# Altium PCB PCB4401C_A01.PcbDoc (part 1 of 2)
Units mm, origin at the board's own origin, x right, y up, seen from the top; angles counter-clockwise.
Board outline 30 x 49 mm, 4 copper layers (Top Layer, Signal Layer 2, Signal Layer 3, Bottom Layer), stack 1.6 mm thick; 91 components, 90 nets, 342 pads, 490 vias.
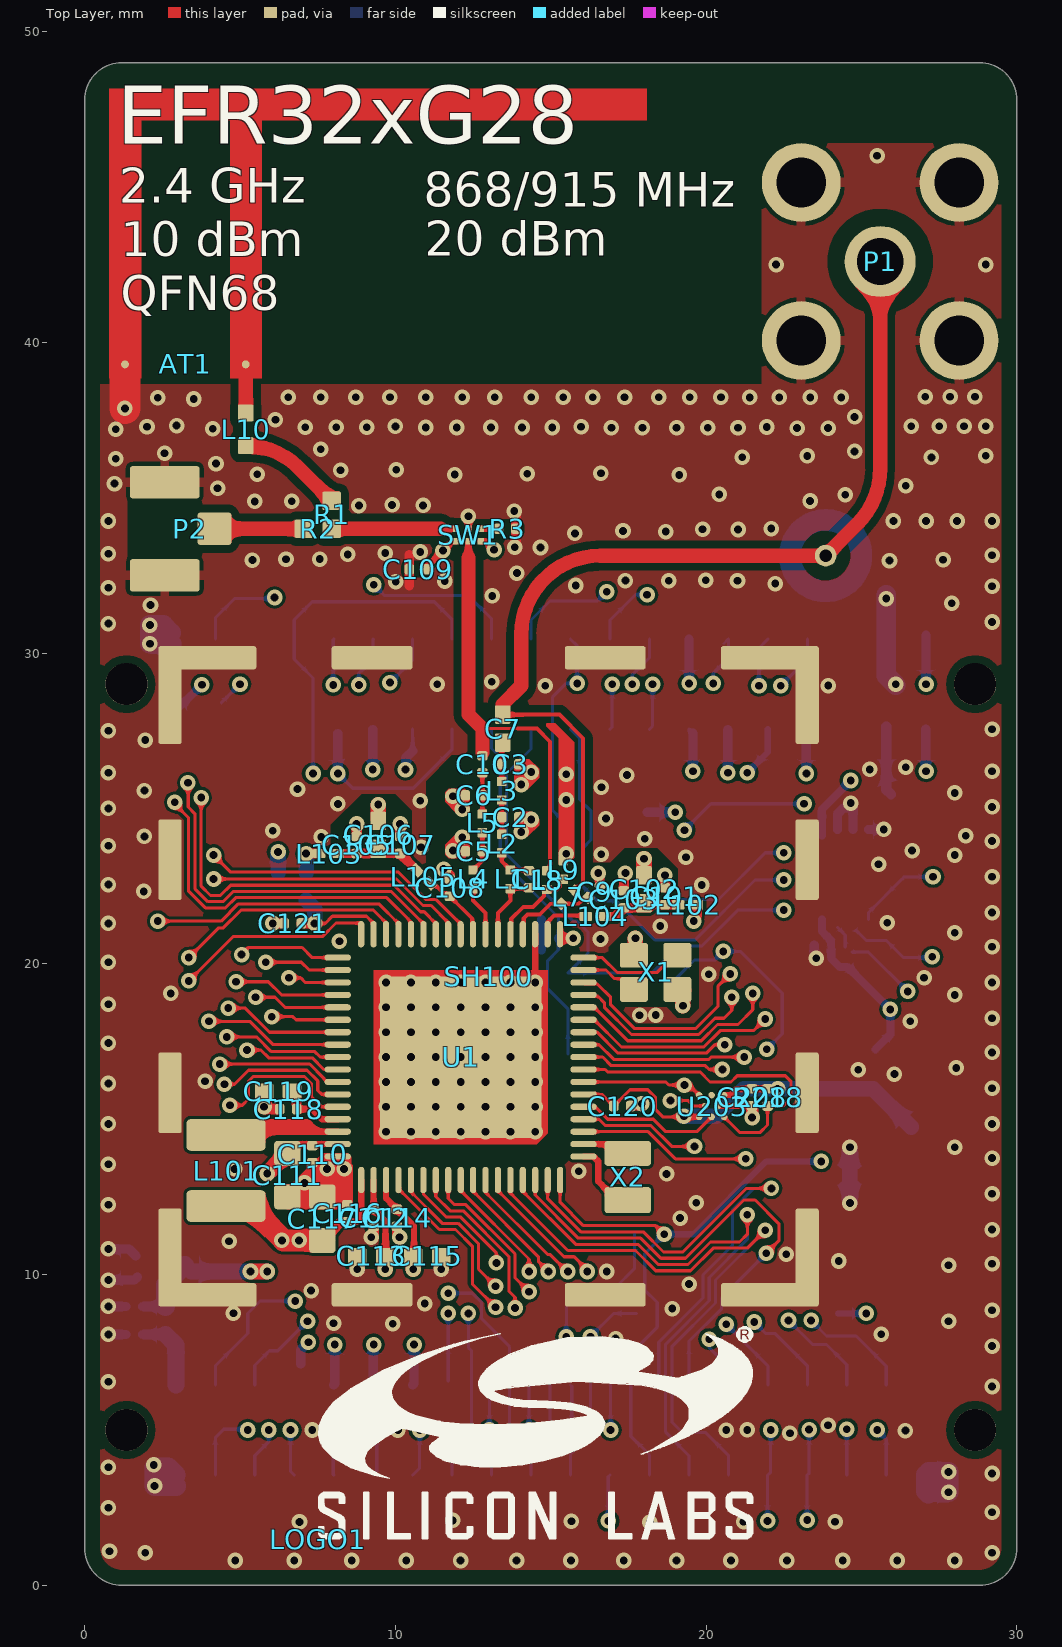
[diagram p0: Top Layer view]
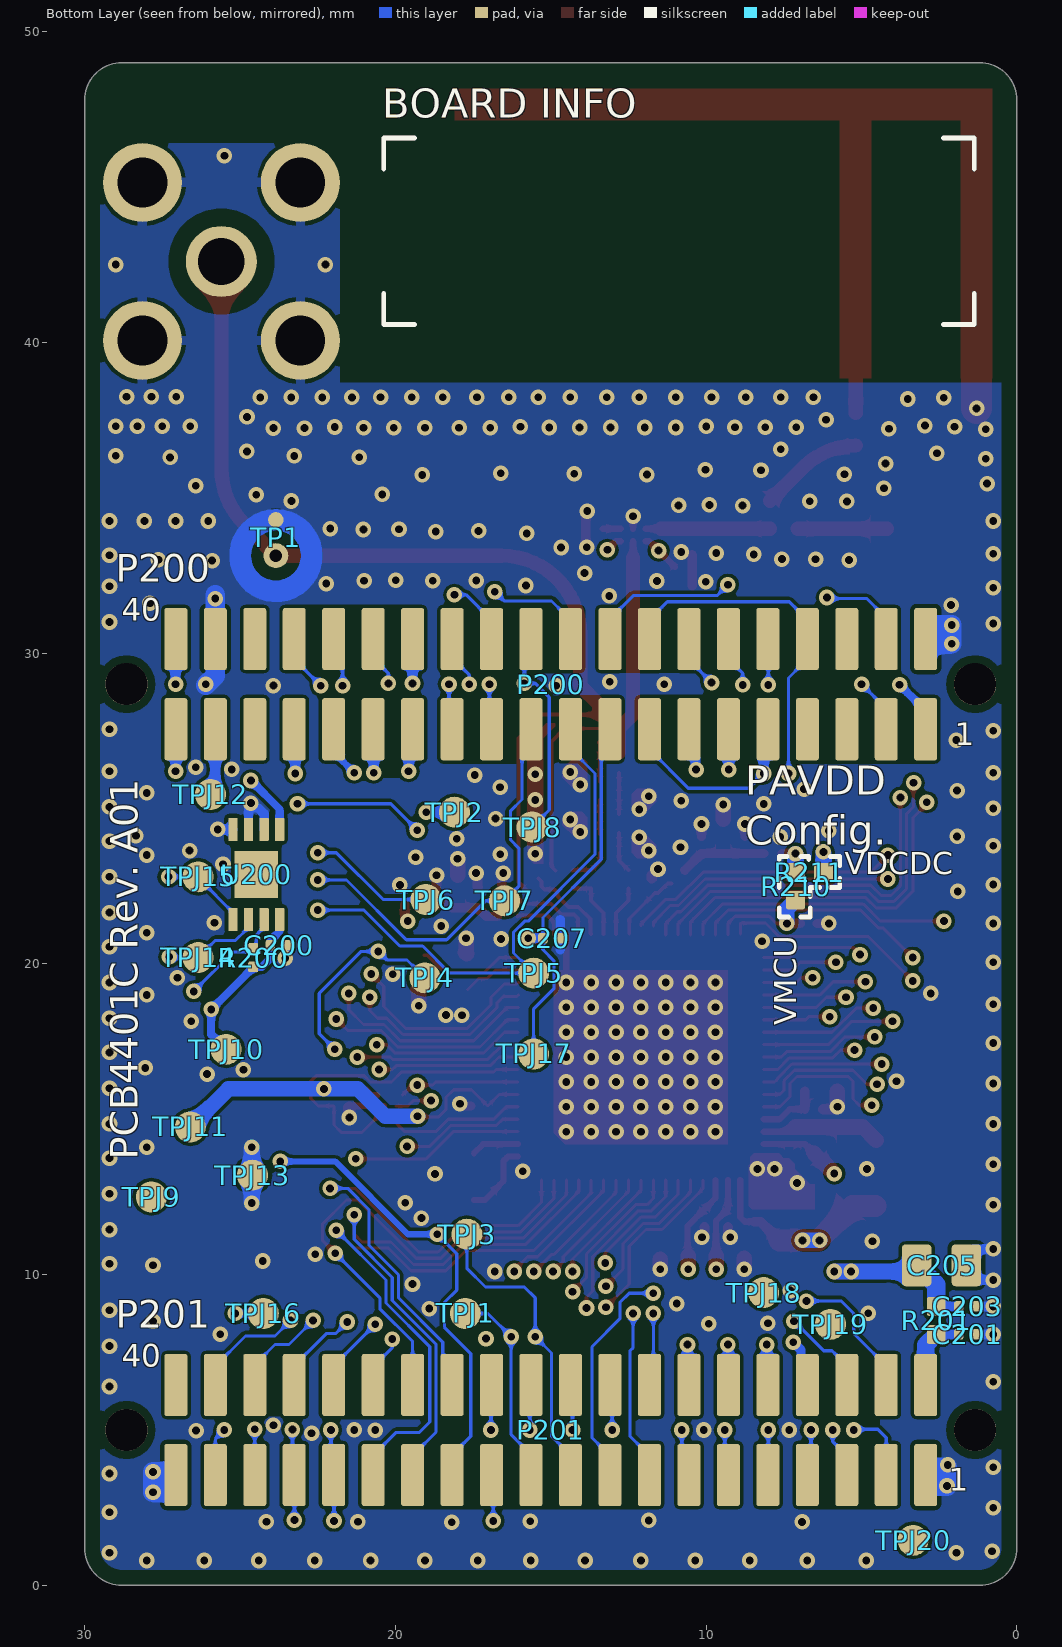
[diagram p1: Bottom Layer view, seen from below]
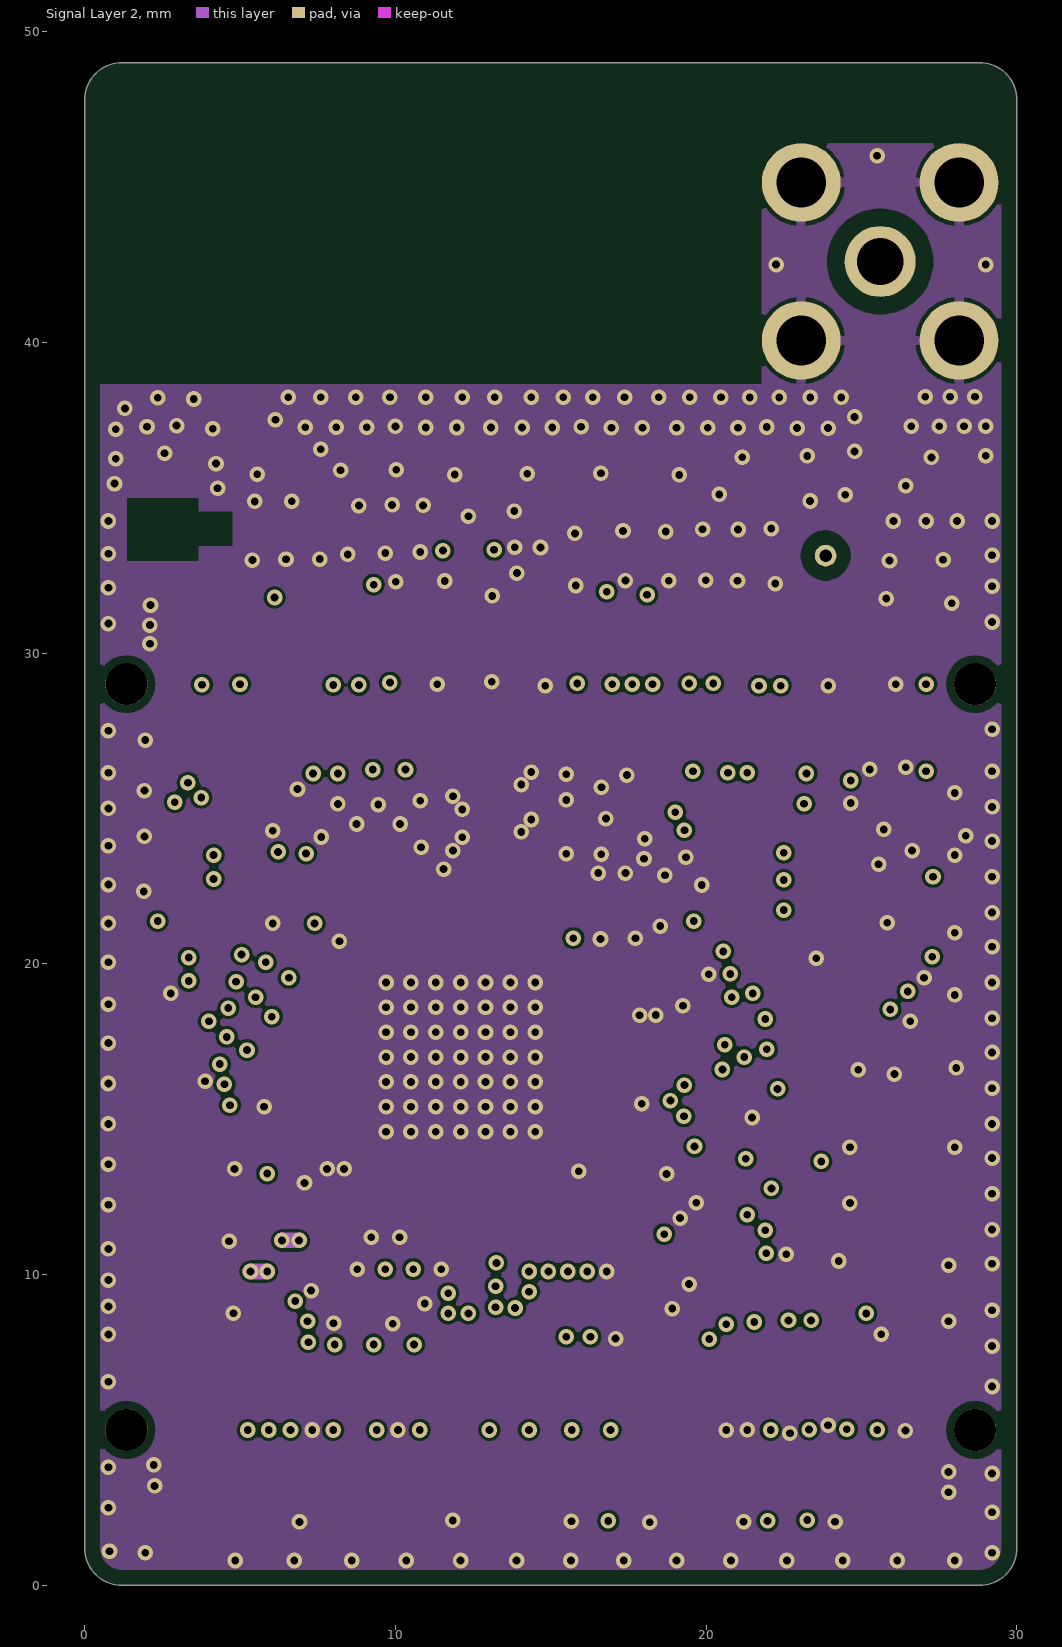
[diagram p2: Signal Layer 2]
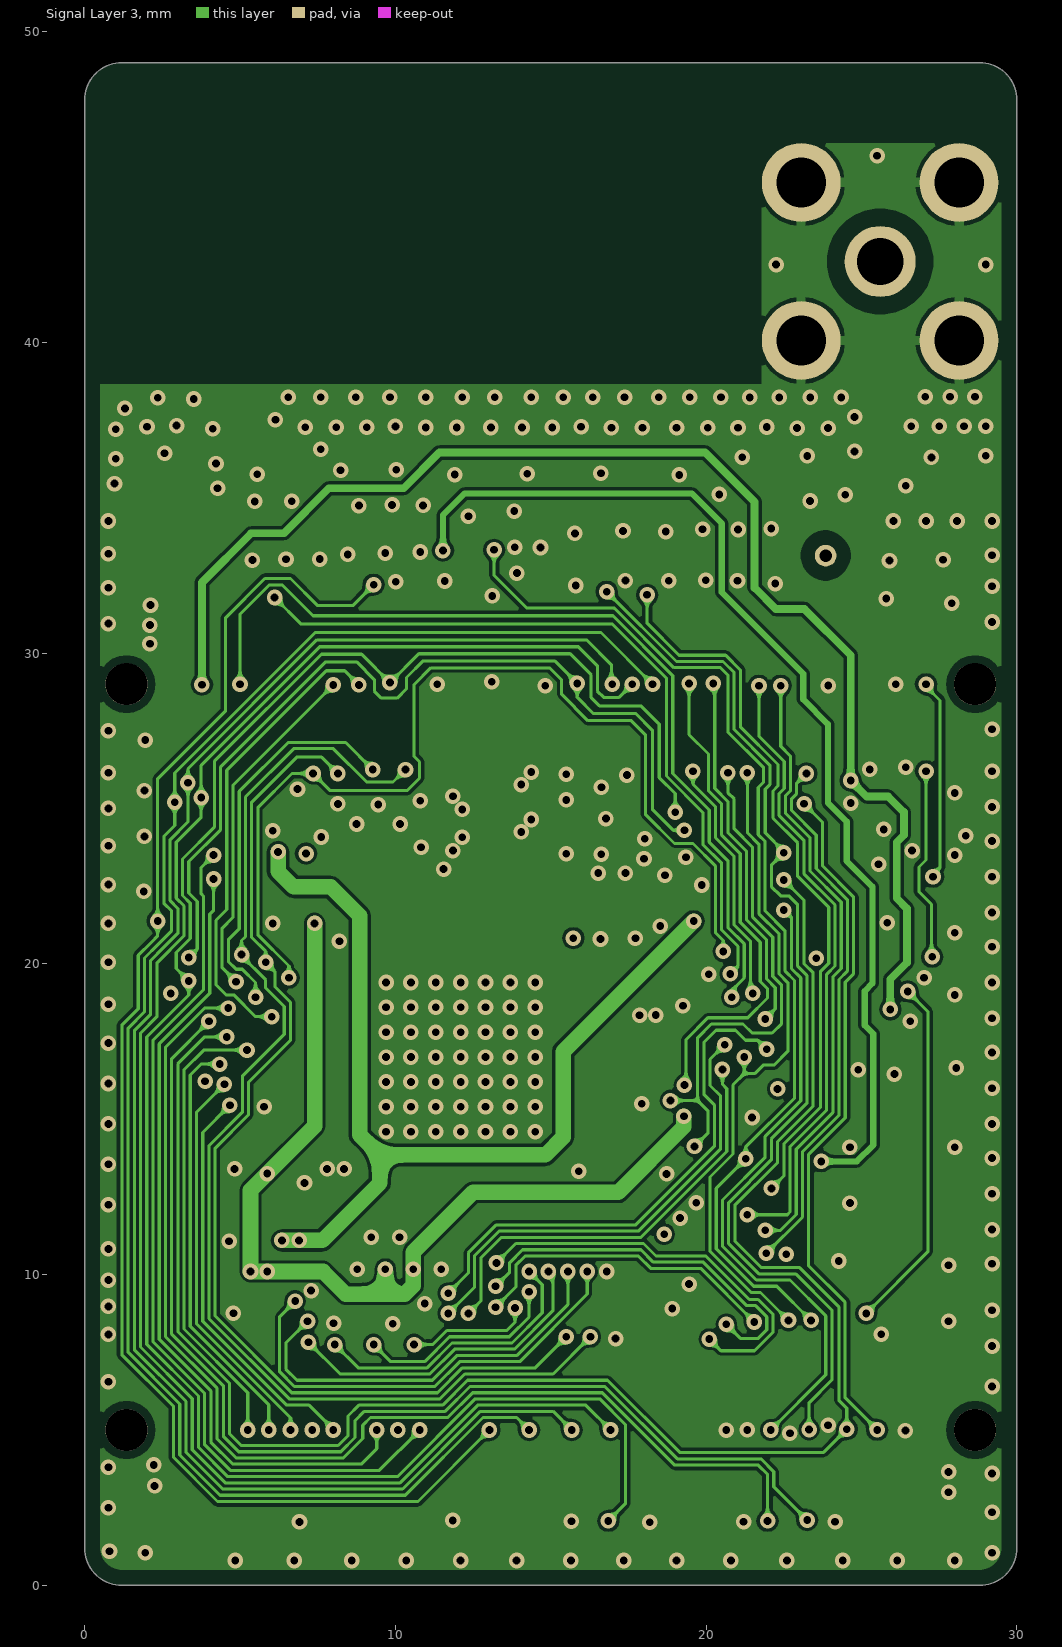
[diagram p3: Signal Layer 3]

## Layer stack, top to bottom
Top Solder: solder mask 0.0102, Solder Resist, Dk 3.5
Top Layer: signal copper 0.035
Dielectric 1: core 0.325, FR-4, Dk 4.2
Signal Layer 2: signal copper 0.018
Dielectric 3: prepreg 0.844, Dk 4.2
Signal Layer 3: signal copper 0.018
Dielectric 2: core 0.325, Dk 4.2
Bottom Layer: signal copper 0.035
Bottom Solder: solder mask 0.0102, Solder Resist, Dk 3.5

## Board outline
0,1.2 0,47.8 cw(c1.2,47.8) 1.2,49 28.8,49 cw(c28.8,47.8) 30,47.8 30,1.2 cw(c28.8,1.2) 28.8,0 1.2,0 cw(c1.2,1.2)

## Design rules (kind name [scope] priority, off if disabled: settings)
AcuteAngle [All] p1: minimum=7.00000000000000E+0001 checktracksonly=FALSE
BoardOutlineClearance [All] p1: gap=0.5 ignorepadtopadclearanceinfootprint=FALSE
Clearance Clearance_50Ohm [InNet('50R*') vs InNet('GND')] p1: gap=0.1 ignorepadtopadclearanceinfootprint=FALSE except(0: Arc-Hole Track-Hole SMDPad-Hole THPad-Hole Via-Hole Fill-Hole Poly-Hole Region-Hole Text-Hole; 0.254: Arc-Poly Track-Poly SMDPad-Poly THPad-Poly Via-Poly Fill-Poly Poly-Poly Poly-Region Poly-Text)
Clearance Clearance_to_Holes [InPadClass('NPTH')] p2: gap=0.254 ignorepadtopadclearanceinfootprint=FALSE except(0: Arc-Hole Track-Hole SMDPad-Hole THPad-Hole Via-Hole Fill-Hole Poly-Hole Region-Hole Text-Hole)
Clearance Clerance_Polygon [InPolygon] p3: gap=0.1 ignorepadtopadclearanceinfootprint=FALSE except(0: Arc-Hole Track-Hole SMDPad-Hole THPad-Hole Via-Hole Fill-Hole Poly-Hole Region-Hole Text-Hole)
Clearance Clearance_General [All] p4: gap=0.1 ignorepadtopadclearanceinfootprint=FALSE except(0: Arc-Hole Track-Hole SMDPad-Hole THPad-Hole Via-Hole Fill-Hole Poly-Hole Region-Hole Text-Hole)
HoleToHoleClearance HoleToHoleClearance_ANT1toPAD [Incomponent ('ANT1') vs ISpad] p1: gap=0 allowstackedmicrovias=TRUE
HoleToHoleClearance HoleToHoleClearance_R1toR2_1 [Incomponent ('R1') vs Incomponent ('R2')] p2: gap=0 allowstackedmicrovias=TRUE
HoleToHoleClearance HoleToHoleClearance_U1toVIA_1 [InComponent ('U1') vs IsVia] p3: gap=0 allowstackedmicrovias=TRUE
HoleToHoleClearance [All] p4: gap=0.254 allowstackedmicrovias=TRUE
MinimumSolderMaskSliver [All] p1: minsoldermaskwidth=0.075
PolygonConnect Polygon_VIA_Connect [IsVia] p1: connectstyle=Direct reliefconductorwidth=0.254 reliefentries=4 polygonreliefangle="90 Angle" airgapwidth=0.254
PolygonConnect PolygonConnect_SH100 [InComponent('SH100')] p2: connectstyle=Direct reliefconductorwidth=0.254 reliefentries=4 polygonreliefangle="90 Angle" airgapwidth=0.127
PolygonConnect PolygonConnect_P1 [InComponent('P1', 'P2')] p3: connectstyle=Relief reliefconductorwidth=0.3 reliefentries=4 polygonreliefangle="90 Angle" airgapwidth=0.127
PolygonConnect [All] p4: connectstyle=NoConnect reliefconductorwidth=0.2 reliefentries=4 polygonreliefangle="90 Angle" airgapwidth=0.125
RoutingVias [All] p1: holewidth=0.3 width=0.65 viastyle="Through Hole" minholewidth=0.25 minwidth=0.5 maxholewidth=1 maxwidth=1.5
ShortCircuit ShortCircuit_ANTtoPAD [InNet('NetAT1_1') vs InNet('GND')] p1: allowed=TRUE
ShortCircuit ShortCircuit_R1toR2_1 [Incomponent ('R1') vs Incomponent ('R2')] p2: allowed=TRUE
ShortCircuit [All] p3: allowed=FALSE
SilkToSilkClearance [All] p1: silktosilkclearance=0.102
SilkToSolderMaskClearance [IsPad] p1: minsilkscreentomaskgap=0.102 clearancetoexposedcopper=TRUE
SolderMaskExpansion [All] p1: expansion=0.051 istentingtop=FALSE
Width 50ohm [InNet('50R*')] p1: maxlimit=0.457 minlimit=0.1 preferedwidth=0.457
Width [All] p2: maxlimit=5.08 minlimit=0.1 preferedwidth=0.125
25 further rules are at their usual default settings.

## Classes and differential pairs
pad class NPTH: P200-M1 P200-M2 P201-M1 P201-M2

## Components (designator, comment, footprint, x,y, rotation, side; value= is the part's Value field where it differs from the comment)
AT1 "INVERTED_F" ANT_INV_F_2.4_GHZ_17.3MM_MIR 0.79,38.84 r0 top locked net-tie
C1 "2P0" C0201_L 14.3,22.72 r90 top
C2 "7P6" C0201_L 13.7,24.72 r0 top
C3 "1P3" C0201_L 13.7,26.42 r180 top
C5 "1P0" C0201_L 12.525,23.62 r180 top
C6 "0P3" C0201_L 12.525,25.42 r0 top
C7 "220P" C0402_L 13.45,27.57 r90 top
C9 "TBD" C0201_L 16.4,22.32 r225 top
C10 "18P" C0201_L 12.8,26.42 r270 top
C101 "TBD" C0201_L 18.675,22.175 r90 top
C102 "1U" C0402_L 18,22.4 r90 top
C103 "100P" C0201_L 17.35,22.075 r90 top
C105 "TBD" C0201_L 8.75,23.825 r90 top
C106 "470N" C0402_L 9.45,24.15 r90 top
C107 "100P" C0201_L 10.15,23.825 r90 top
C108 "100P" C0201_L 11.75,22.45 r90 top
C109 "100P" C0201_L 10.724,32.695 r180 top
C110 "100N" C0201_L 7.325,13.875 r270 top
C111 "10U" C0603_L 6.525,13.2 r270 top
C112 "10N" C0201_L 9.3,11.825 r270 top
C113 "1U" C0402_L 9.225,10.6 r180 top
C114 "100N" C0201_L 10.05,11.825 r270 top
C115 "1U" C0402_L 11.025,10.6 r0 top
C116 "100N" C0201_L 8.45,11.975 r90 top
C117 "4U7" C0603_L 7.65,11.8 r90 top
C118 "100N" C0201_L 6.55,15.325 r180 top
C119 "1U" C0402_L 6.225,15.9 r180 top
C120 "100N" C0201_L 17.3,15.425 r0 top
C121 "100N" C0201_L 6.7,21.3 r180 top
C200 "100N" C0201_L 23.75,20.6 r180 bottom
C201 "100N" C0201_L 1.6,8.075 r180 bottom
C203 "100N" C0201_L 1.6,8.975 r180 bottom
C205 "10U" C0805_L 2.425,10.3 r180 bottom
C207 "100N" C0201_L 14.975,20.825 r180 bottom
C208 "100N" C0201_L 21.475,15.7 r270 top
Designator39 "Comment" PCB_SPEC_4_LAYER -68.7,108.2 r0 top
L1 "1N5" COIL_0201_L 13.7,22.72 r90 top
L2 "1N3" COIL_0201_L 13.425,23.87 r90 top
L3 "13N" COIL_0201_L 13.425,25.57 r90 top
L4 "3N0" COIL_0201_L 12.5,22.72 r90 top
L5 "8N2" COIL_0201_L 12.8,24.52 r90 top
L7 "18N" COIL_0201_L 15.55,22.145 r45 top
L8 "3N1" COIL_0201_L 14.875,22.695 r90 top
L9 "1N8" COIL_0201_L 15.4,23.02 r90 top
L10 "0R" COIL_0402_L 5.184,37.2 r90 top
L101 "2U2" COIL_1008_L 4.55,13.35 r270 top
L102 "BLM03AG700SN1D" COIL_MUR_BLM03_0201 19.4,21.9 r0 top
L103 "0R" COIL_MUR_BLM03_0201 7.85,23.55 r180 top
L104 "0R" COIL_MUR_BLM03_0201 16.425,21.525 r180 top
L105 "BLM03PG330SN1D" COIL_MUR_BLM03_0201 10.9,22.8 r315 top
LOGO1 "Comment" LOGO_SILABS_W14.0 7.501,1.49 r0 top
P1 "SMA" TE_SMA_1814832_TH_VER 25.6,42.6 r0 top
P2 "U.FL" COAX_HIROSE_U.FL_CL331-0471 2.578,34 r270 top
P200 "SOCKET_WCON_2X20_1.27MM_SMD" SAM_SFC-120-T2-D-A-2X20_SNUM 15,29 r0 bottom locked
P201 "SOCKET_WCON_2X20_1.27MM_SMD" SAM_SFC-120-T2-D-A-2X20_SNUM 15,5 r0 bottom locked
R1 "0R" R0402_L 7.95,34.45 r90 top
R2 "0R" R0402_L 7.5,34 r180 top
R3 "50R" R0201_L#1 13.6,34 r0 top
R200 "10K" R0201_L#2 24.575,20.2 r270 bottom
R201 "0R" R0402_L 2.6,8.525 r90 bottom
R210 "0R" R0402_L 7.125,22.5 r270 bottom
R211 "0R" R0402_L 6.675,22.95 r0 bottom
R218 "330K" R0201_L#1 21.975,15.7 r90 top
SH100 "RF_SHIELD_FRAME_36103205S" shield_21x21mm 13,19.6 r0 top locked
SW1 "BGS12WN6" XFDFN-6 12.35,33.8 r180 top
TP1 "TP_RF" "TP_INGUN_50_OHM_CLOSED OPENVIA" 23.845,33.135 r0 bottom
TPJ1 "TPJ_SMD" TP_1.0_SMD 17.75,8.75 r90 bottom locked
TPJ2 "TPJ_SMD" TP_1.0_SMD 18.1,24.88 r90 bottom locked
TPJ3 "TPJ_SMD" TP_1.0_SMD 17.7,11.3 r90 bottom locked
TPJ4 "TPJ_SMD" TP_1.0_SMD 19.05,19.55 r90 bottom locked
TPJ5 "TPJ_SMD" TP_1.0_SMD 15.55,19.7 r90 bottom locked
TPJ6 "TPJ_SMD" TP_1.0_SMD 19.02,22.07 r90 bottom locked
TPJ7 "TPJ_SMD" TP_1.0_SMD 16.49,22.03 r90 bottom locked
TPJ8 "TPJ_SMD" TP_1.0_SMD 15.6,24.4 r90 bottom locked
TPJ9 "TPJ_SMD" TP_1.0_SMD 27.85,12.5 r90 bottom locked
TPJ10 "TPJ_SMD" TP_1.0_SMD 25.45,17.25 r90 bottom locked
TPJ11 "TPJ_SMD" TP_1.0_SMD 26.6,14.75 r90 bottom locked
TPJ12 "TPJ_SMD" TP_1.0_SMD 25.95,25.45 r90 bottom locked
TPJ13 "TPJ_SMD" TP_1.0_SMD 24.6,13.2 r90 bottom locked
TPJ14 "TPJ_SMD" TP_1.0_SMD 26.35,20.2 r90 bottom locked
TPJ15 "TPJ_SMD" TP_1.0_SMD 26.35,22.8 r90 bottom locked
TPJ16 "TPJ_SMD" TP_1.0_SMD 24.25,8.75 r90 bottom locked
TPJ17 "TPJ_SMD" TP_1.0_SMD 15.55,17.1 r90 bottom locked
TPJ18 "TPJ_SMD" TP_1.0_SMD 8.15,9.42 r90 bottom locked
TPJ19 "TPJ_SMD" TP_1.0_SMD 6,8.4 r90 bottom locked
TPJ20 "TPJ_SMD" TP_1.0_SMD 3.34,1.45 r90 bottom locked
U1 "EFR32ZG28B322F1024IM68" QFN68_M040_8.0X8.0_EP_SL 12.1,17 r180 top
U200 "M24C02" TDFN8_M050_2.0X3.0_EP 24.475,22.875 r270 bottom
U203 "MX25R8035F" BGA8_M040_1.24X1.75_WLCSP 20.175,15.425 r270 top
X1 "39.000 MHz" KDS_DSX211SH_2016 18.375,19.725 r180 top
X2 "32.768 kHz" X_MCS_CM8V-T1A 17.475,13.15 r270 top

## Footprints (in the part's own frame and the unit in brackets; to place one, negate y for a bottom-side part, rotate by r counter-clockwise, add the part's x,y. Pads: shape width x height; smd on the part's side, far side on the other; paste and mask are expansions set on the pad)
ANT_INV_F_2.4_GHZ_17.3MM_MIR [mil] "Antenna inverted F, 2.4 GHz, 17.3 mm (MIR)"
  round 10 smd paste-5.04 mask-5.04: 1(173,17.72) 2(20.01,17.72)
  Top Layer region: 0.36,367.2 681,367.2 681,327.07 193.36,327.07 193.36,0 153.36,0 153.36,327.07 40.36,327.07 40.36,0 20.36,0 0.36,0
BGA8_M040_1.24X1.75_WLCSP [mm] "BGA, 8 pin. U100"
  round 0.21 smd mask+0.038: A1(-0.35,0.4) A3(0.35,0.4) B2(0,0.2) C1(-0.35,0) C3(0.35,0) D2(0,-0.2) E1(-0.35,-0.4) E3(0.35,-0.4)
  body extent -0.63,-0.89 0.63,0.88, height 0.52
C0201_L [mm] "Capacitor, Chip; 0.60 mm L X 0.30 mm W X 0.33 mm H body"
  rrect52% 0.31x0.34 smd: 1(-0.275,0) 2(0.275,0)
  body extent -0.3,-0.15 0.3,0.15, height 0.3
C0402_L [mm] "Chip Capacitor, 2-Leads, Body 1.0x0.5mm, IPC High Density"
  rrect20% 0.6x0.5 smd mask+0.051: 1(-0.45,0) 2(0.45,0)
  body extent -0.5,-0.25 0.5,0.25, height 0.6
C0603_L [mm] "Capacitor, 0603, High Density (C)"
  rrect25% 0.8x0.85 smd: 1(-0.7,0) 2(0.7,0)
  body extent -0.8,-0.4 0.8,0.4, height 0.95
C0805_L [mm] "Capacitor, 0805"
  rrect25% 0.95x1.35 smd: 1(-0.8,0) 2(0.8,0)
  body extent -1.1,-0.72 1.1,0.72, height 1.45
COAX_HIROSE_U.FL_CL331-0471 [mm] "COAX_HIROSE_U.FL_CL331-0471"
  rrect20% 1.05x1.1 smd mask+0.051: 1(0,1.6)
  rrect20% 1.05x2.25 smd mask+0.051: 2(-1.5,0) 3(1.5,0)
  Top Layer pour cut-out: -0.85,0.9 0.85,0.9 0.85,0.9 0.85,-1.2 -0.85,-1.2 -0.85,-1.2
  body extent -1.3,-1.55 1.3,1.3, height 0.9
COIL_0201_L [mm] "JELF243C-0021"
  rrect10% 0.3x0.3 smd: 1(-0.3,0) 2(0.3,0)
  body extent -0.32,-0.17 0.32,0.17, height 0.33
COIL_0402_L [mm] "COIL_0402_L"
  rrect20% 0.55x0.5 smd mask+0.051: 1(-0.525,0) 2(0.525,0)
  body extent -0.5,-0.25 0.5,0.25, height 0.5
COIL_1008_L [mil] "Chip Inductors, 1008 (2520), Coilcraft (190207)"
  rrect25% 40x100 smd: 1(-45,0) 2(45,0)
  body extent -58,-55 57,55, height 80
COIL_MUR_BLM03_0201 [mm] "COIL_MUR_BLM03_0201"
  rrect25% 0.4x0.3 smd mask+0.051: 1(-0.3,0) 2(0.3,0)
  body extent -0.3,-0.15 0.3,0.15, height 0.95
KDS_DSX211SH_2016 [mm] "Copy of Silabs CE  X_KDS_DSX211SH_2.0X1.65-4"
  rrect20% 0.9x0.8 smd mask+0.051: 1(-0.7,-0.55) 2(0.7,-0.55) 3(0.7,0.55) 4(-0.7,0.55)
  body extent -1.07,-0.87 1.08,0.88, height 0.5
LOGO_SILABS_W14.0 [mm] "LOGO_SILABS_W14.0"
  silkscreen extent 0.03,0 13.99,6.83
PCB_SPEC_4_LAYER [mm]
QFN68_M040_8.0X8.0_EP_SL [mm]
  rrect5% 5.2x5.2 smd paste-4.2 mask-4.2: 0(0,0)
  oval 0.85x0.2 smd paste+0 mask+0.06: 1(-3.955,3.2) 2(-3.955,2.8) 3(-3.955,2.4) 4(-3.955,2) 5(-3.955,1.6) 6(-3.955,1.2) 7(-3.955,0.8) 8(-3.955,0.4) 9(-3.955,0) 10(-3.955,-0.4) 11(-3.955,-0.8) 12(-3.955,-1.2) 13(-3.955,-1.6) 14(-3.955,-2) 15(-3.955,-2.4) 16(-3.955,-2.8) 17(-3.955,-3.2) 35(3.955,-3.2) 36(3.955,-2.8) 37(3.955,-2.4) 38(3.955,-2) 39(3.955,-1.6) 40(3.955,-1.2) 41(3.955,-0.8) 42(3.955,-0.4) 43(3.955,0) 44(3.955,0.4) 45(3.955,0.8) 46(3.955,1.2) 47(3.955,1.6) 48(3.955,2) 49(3.955,2.4) 50(3.955,2.8) 51(3.955,3.2)
  oval 0.2x0.85 smd paste+0 mask+0.06: 18(-3.2,-3.955) 19(-2.8,-3.955) 20(-2.4,-3.955) 21(-2,-3.955) 22(-1.6,-3.955) 23(-1.2,-3.955) 24(-0.8,-3.955) 25(-0.4,-3.955) 26(0,-3.955) 27(0.4,-3.955) 28(0.8,-3.955) 29(1.2,-3.955) 30(1.6,-3.955) 31(2,-3.955) 32(2.4,-3.955) 33(2.8,-3.955) 34(3.2,-3.955) 52(3.2,3.955) 53(2.8,3.955) 54(2.4,3.955) 55(2,3.955) 56(1.6,3.955) 57(1.2,3.955) 58(0.8,3.955) 59(0.4,3.955) 60(0,3.955) 61(-0.4,3.955) 62(-0.8,3.955) 63(-1.2,3.955) 64(-1.6,3.955) 65(-2,3.955) 66(-2.4,3.955) 67(-2.8,3.955) 68(-3.2,3.955)
  Top Layer pour cut-out: -3.505,-3.31 -3.31,-3.505 3.31,-3.505 3.505,-3.31 3.505,3.309 3.309,3.505 -3.31,3.505 -3.505,3.309
  Top Layer region: 2.8,-2.8 -2.8,-2.8 -2.8,2.45 -2.45,2.8 2.8,2.8
  body extent -4,-4 4,4, height 0.86
R0201_L#1 [mm] "Resistor, Chip; 0.60 mm L X 0.30 mm W X 0.28 mm H body"
  rrect52% 0.31x0.34 smd: 1(-0.275,0) 2(0.275,0)
  body extent -0.3,-0.15 0.3,0.15, height 0.23
R0201_L#2 [mm] "Resistor (Chip2PinSM127P600-8N) (170921)"
  rrect25% 0.34x0.32 smd: 1(-0.3,0) 2(0.3,0)
  body extent -0.32,-0.13 0.32,0.13, height 0.3
R0402_L [mm] "Chip Resistor, 2-Leads, Body 1.0x0.5mm, IPC High Density (170210)"
  rrect20% 0.6x0.6 smd mask+0.051: 1(-0.45,0) 2(0.45,0)
  body extent -0.5,-0.25 0.5,0.25, height 0.6
SAM_SFC-120-T2-D-A-2X20_SNUM [mm]
  rrect20% 0.74x2 smd mask+0.05: 1(-12.065,1.45) 2(-12.065,-1.45) 3(-10.795,1.45) 4(-10.795,-1.45) 5(-9.525,1.45) 6(-9.525,-1.45) 7(-8.255,1.45) 8(-8.255,-1.45) 9(-6.985,1.45) 10(-6.985,-1.45) 11(-5.715,1.45) 12(-5.715,-1.45) 13(-4.445,1.45) 14(-4.445,-1.45) 15(-3.175,1.45) 16(-3.175,-1.45) 17(-1.905,1.45) 18(-1.905,-1.45) 19(-0.635,1.45) 20(-0.635,-1.45) 21(0.635,1.45) 22(0.635,-1.45) 23(1.905,1.45) 24(1.905,-1.45) 25(3.175,1.45) 26(3.175,-1.45) 27(4.445,1.45) 28(4.445,-1.45) 29(5.715,1.45) 30(5.715,-1.45) 31(6.985,1.45) 32(6.985,-1.45) 33(8.255,1.45) 34(8.255,-1.45) 35(9.525,1.45) 36(9.525,-1.45) 37(10.795,1.45) 38(10.795,-1.45) 39(12.065,1.45) 40(12.065,-1.45)
  round 1.35 hole 1.35 unplated paste-5.563 mask-5.563: M1(13.652,0) M2(-13.652,0)
  body extent -14.29,-2.1 14.29,2.16, height 4.67
shield_21x21mm [mm] "RF_SHIELD wurth 3613205"
  rrect20% 0.75x3.15 smd paste+0 mask+0.05: 1(-10.25,-9.05) 1(-10.25,9.05) 1(10.25,-9.05) 1(10.25,9.05)
  rrect20% 0.75x2.6 smd paste+0 mask+0.05: 1(-10.25,-3.75) 1(-10.25,3.75) 1(10.25,-3.75) 1(10.25,3.75)
  rrect20% 3.15x0.75 smd paste+0 mask+0.05: 1(-9.05,-10.25) 1(-9.05,10.25) 1(9.05,-10.25) 1(9.05,10.25)
  rrect20% 2.6x0.75 smd paste+0 mask+0.05: 1(-3.75,-10.25) 1(-3.75,10.25) 1(3.75,-10.25) 1(3.75,10.25)
  body extent -13,-13 12.99,12.99, height 5.08
TDFN8_M050_2.0X3.0_EP [mm] "TDFN8_M050_2.0x3.0_EP"
  rrect20% 0.75x0.3 smd mask+0.051: 1(-1.45,0.75) 2(-1.45,0.25) 3(-1.45,-0.25) 4(-1.45,-0.75) 5(1.45,-0.75) 6(1.45,-0.25) 7(1.45,0.25) 8(1.45,0.75)
  rect 1.5x1.4 smd mask+0.051: 9(0,0)
  body extent -1.5,-1 1.5,1, height 1.01
TE_SMA_1814832_TH_VER [mm]
  round 2.286 hole 1.5: 1(0,0)
  round 2.54 hole 1.6: 2(-2.54,-2.54) 3(2.54,-2.54) 4(2.54,2.54) 5(-2.54,2.54)
  Multi-Layer pour cut-out: 0,-1.7 -0.651,-1.571 -1.202,-1.202 -1.571,-0.651 -1.7,0 -1.7,0 -1.571,0.651 -1.202,1.202 -0.651,1.571 0,1.7 0,1.7 0.651,1.571 1.202,1.202 1.571,0.651 1.7,0 1.7,0 1.571,-0.651 1.202,-1.202 0.651,-1.571 0,-1.7
  body extent -3.2,-3.2 3.2,3.2, height 9.5
TP_1.0_SMD [mm] "Test Point, 1.0 mm, SMD"
  round 1 smd paste-0.501: 1(0,0)
  body extent -0.2,-0.2 0.2,0.2, height 0.01
"TP_INGUN_50_OHM_CLOSED OPENVIA" [mm] "TP_INGUN_50_OHM_CLOSED"
  round 0.8 / inner round 0.7 / far side round 0.7 hole 0.4 mask+0: 1(0,0)
  round 0.5 smd paste-0.255 mask-0.41: 2(0,-1.15)
  Top Layer pour cut-out: 0,-0.8 0.4,-0.693 0.693,-0.4 0.8,0 0.693,0.4 0.4,0.693 0,0.8 0,0.8 -0.347,0.721 -0.625,0.499 -0.78,0.178 -0.78,-0.178 -0.625,-0.499 -0.347,-0.721 0,-0.8
  Top Layer lines w0.7: -1.15,0 ccw(c0,0) 0,-1.15 ccw(c0,0) -1.15,0
X_MCS_CM8V-T1A [mm] "Crystal MCS CM8V-T1A (2 pin)"
  rrect25% 0.8x1.5 smd mask+0.051: 1(-0.75,0)
  rrect25% 0.85x1.5 smd mask+0.051: 2(0.75,0)
  body extent -1,-0.6 1,0.6, height 0.6
XFDFN-6 [mm] "Infineon PG-TSNP-6-10"
  rect 0.2x0.2 smd paste-1 mask+0.025: 1(-0.4,-0.2) 2(0,-0.2) 3(0.4,-0.2) 4(0.4,0.2) 5(0,0.2) 6(-0.4,0.2)
  body extent -0.55,-0.35 0.55,0.35, height 0.4

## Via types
v1: diameter 0.5, hole 0.25, Top Layer to Bottom Layer, tented both sides, 490 vias

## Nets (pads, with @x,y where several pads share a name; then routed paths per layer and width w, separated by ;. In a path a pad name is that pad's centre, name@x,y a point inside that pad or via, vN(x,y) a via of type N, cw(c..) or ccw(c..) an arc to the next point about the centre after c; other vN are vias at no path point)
3V3: C200.1 P200.1 R200.2 TPJ10.1 U200.1 U200.8 | length 52.5
  Signal Layer 3 w0.25: v1(3.775,28.982) 3.775,32.273 5.357,33.855 6.414,33.855 7.86,35.301 10.263,35.301 11.42,36.458 19.965,36.458 21.56,34.863 21.56,32.097 22.237,31.421 23.161,31.421 24.65,29.931 v1(24.65,25.9) 25.169,25.381 25.863,25.381 26.362,24.882 26.362,24.143 26.133,23.913 26.133,22.108 26.459,21.781 26.459,20.037 25.927,19.505 v1(25.927,18.533)
  Bottom Layer w0.254: P200.1@2.935,27.55 2.935,28.142 v1(3.775,28.982) ; U200.8@23.725,21.425 23.725,21.05 24.025,20.75 C200.1@24.025,20.625 ; U200.1@23.725,24.125 23.725,24.975 v1(24.65,25.9) ; C200.1@24.025,20.6 24.025,20.175 24.3,19.9 R200.2@24.525,19.9 ; R200.2@24.575,19.885 v1(25.927,18.533) 25.927,17.727 TPJ10.1@25.45,17.25
5V: P200.37 TPJ12.1 | length 2.2
  Bottom Layer w0.33: P200.37@25.795,27.635 P200.37@25.795,27.55 25.795,25.605 TPJ12.1@25.95,25.45
50R_IFA: AT1.1 L10.2 | length 1.6
  Top Layer w0.457: L10.2@5.184,37.725 AT1.1@5.184,39.29
50R_L10: L10.1 R1.2 | length 3.4
  Top Layer w0.457: L10.1@5.184,36.675 cw(c5.184,34.283) 6.876,35.974 R1.2@7.95,34.9
50R_P1: C7.2 L7.2 P1.1 TP1.1 | length 32.1
  Top Layer w0.125: C7.2@13.45,28.02 15.28,28.02 16.04,27.26 16.04,22.635 L7.2@15.762,22.357
  Top Layer w0.457: C7.2@13.45,28.02 13.45,28.35 14.05,28.95 14.05,30.595 cw(c16.59,30.595) 16.59,33.135 TP1.1@23.845,33.135 24.856,34.146 ccw(c23.06,35.942) 25.6,35.942 P1.1@25.6,42.6
50R_P2: P2.1 R2.2 | length 2.9
  Top Layer w0.457: P2.1@4.178,34 R2.2@7.05,34
50R_R1: R1.1 R2.1 SW1.3 | length 4
  Top Layer w0.2: 11.45,34 SW1.3@11.95,34
  Top Layer w0.457: R2.1@7.95,34 11.45,34
50R_SW: C10.1 L8.2 SW1.5 | length 13.5
  Top Layer w0.1: 12.8,27.57 13.942,27.57
  Top Layer w0.125: 13.942,27.57 14.555,27.57 14.98,27.145 14.98,23.125 L8.2@14.85,22.995
  Top Layer w0.2: 12.35,33.068 SW1.5@12.35,33.6
  Top Layer w0.457: 12.35,33.068 12.35,28.02 12.8,27.57 C10.1@12.8,26.8
BOARD_ID_SCL: P200.39 TPJ14.1 U200.6 | length 10.4
  Signal Layer 3 w0.1: v1(27.075,26.2) 27.075,23.341 26.85,23.116 26.85,22.316 27.25,21.916 v1@27.25,20.275
  Bottom Layer w0.1: U200.6@24.825,21.075 25.15,20.75 25.8,20.75 TPJ14.1@26.35,20.2 v1@27.375,20.2
  Bottom Layer w0.3: v1@27.065,26.21 P200.39@27.065,27.55
  other v1: 27.275,20.225
BOARD_ID_SDA: P200.40 TPJ15.1 U200.5 | length 10.7
  Signal Layer 3 w0.1: v1@27.075,28.925 27.526,28.474 27.526,23.101 v1@27.3,22.875
  Bottom Layer w0.102: U200.5@25.225,21.425 25.225,21.65 26.3,22.725 TPJ15.1@26.325,22.725 ; TPJ15.1@26.35,22.8 v1(27.3,22.8) ; P200.40@27.05,30.6 P200.40@27.075,30.575
  Bottom Layer w0.3: v1(27.075,29) P200.40@27.075,30.575
BOARD_ID_WP: R200.1 TPJ16.1 U200.7 | length 15.4
  Signal Layer 3 w0.1: v1(25.15,8.75) 27.135,10.735 27.135,18.466 v1(26.487,19.114)
  Bottom Layer w0.1: U200.7@24.225,21.175 24.475,20.925 R200.1@24.475,20.55 ; R200.1@24.7,20.375 25.226,20.375 v1(26.487,19.114)
  Bottom Layer w0.2: TPJ16.1@24.25,8.75 v1(25.15,8.75)
EFR32_PA0: P200.22 P201.37 TPJ8.1 U1.32 | length 71.1
  Top Layer w0.1: v1(3.35,20.2) 4.3,21.15 4.45,21.15 5.03,21.73 9.295,21.73 9.7,21.325 U1.32@9.7,20.955 U1.32@9.7,20.935
  Signal Layer 3 w0.1: v1(3.35,20.2) 3.625,20.475 3.625,20.855 3.625,22.006 3.35,22.281 3.35,23.292 4.375,24.317 4.375,26.338 7.754,29.717 8.753,29.717 9.325,29.145 9.325,28.775 9.55,28.55 10.057,28.55 10.36,28.853 10.36,29.214 10.896,29.75 15.125,29.75 v1(15.85,29.025) 15.85,28.575 16.368,28.057 17.734,28.057 18.27,27.52 18.27,24.976 18.946,24.3 v1(19.3,24.3) ; v1(23.15,25.15) 23.742,24.558 23.742,23.152 24.746,22.148 24.746,19.683 24.476,19.413 24.476,15.047 23.299,13.87 23.299,10.278 24.471,9.106 24.471,6.037 v1(25.504,5.004)
  Bottom Layer w0.1: TPJ8.1@15.6,24.4 15.05,24.95 15.05,28.575 15.5,29.025 v1(15.85,29.025) 15.85,30.235 P200.22@15.635,30.45 ; v1(19.3,24.3) 20.15,25.15 v1(23.15,25.15) ; v1(25.504,5.004) 25.795,4.713 P201.37@25.795,3.55
EFR32_PA1: P200.14 P201.23 TPJ2.1 U1.34 | length 74.7
  Top Layer w0.1: v1(3.35,19.45) 4.775,20.875 7.65,20.875 8.09,21.315 8.877,21.315 8.9,21.292 U1.34@8.9,20.955
  Signal Layer 3 w0.1: v1(16.85,2.075) 17.4,2.625 17.4,5.176 16.576,6 12.568,6 10.068,3.5 4.606,3.5 3.663,4.444 3.663,6.092 2,7.754 2,17.647 3.35,18.997 v1(3.35,19.45) 2.95,19.85 2.95,20.366 3.4,20.816 3.4,21.949 3.15,22.199 3.15,23.375 4.175,24.4 4.175,26.516 7.622,29.963 8.912,29.963 v1(9.825,29.05) 10.754,29.979 15.621,29.979 16.3,29.3 16.3,28.567 16.564,28.303 17.897,28.303 18.491,27.709 18.491,25.993 19.005,25.479 v1(19.005,24.88)
  Bottom Layer w0.1: v1(9.825,29.05) 10.555,29.78 P200.14@10.555,30.45 ; v1(16.85,2.075) 16.85,3.495 P201.23@16.905,3.55
  Bottom Layer w0.3: TPJ2.1@18.1,24.88 v1(19.005,24.88)
EFR32_PA2: P200.13 P201.21 TPJ1.1 U1.35 | length 50.3
  Top Layer w0.1: v1(5.05,20.3) 5.275,20.525 7,20.525 7.325,20.2 U1.35@8.145,20.2
  Signal Layer 3 w0.1: v1@10.325,26.125 10.2,26.125 9.925,25.85 9.075,25.85 8,26.925 6.725,26.925 5.175,25.375 5.175,20.875 5.05,20.75 v1(5.05,20.3) 5.05,20.259 5.825,19.484 5.825,19.225 6.425,18.625 6.425,17.733 5.075,16.383 5.075,15.225 4,14.15 4,8.583 6.583,6 11.437,6 12.237,6.8 15.075,6.8 v1(16.275,8)
  Bottom Layer w0.1: v1@10.325,26.125 v1(10.325,26.25) ; P200.13@10.555,26.85 P200.13@10.555,27.55 ; P201.21@15.635,3.55 15.635,4.21 16.275,4.85 v1(16.275,8) 17.025,8.75 TPJ1.1@17.75,8.75
  Bottom Layer w0.3: v1(10.325,26.25) 10.325,26.62 P200.13@10.555,26.85
EFR32_PA3: P200.9 P200.15 P201.19 TPJ3.1 U1.36 | length 53.3
  Top Layer w0.1: v1(5.825,20.05) 6.975,20.05 7.225,19.8 U1.36@8.145,19.8
  Signal Layer 3 w0.1: v1(8.15,26.125) 7.625,26.65 6.825,26.65 5.375,25.2 5.375,20.85 5.825,20.4 v1(5.825,20.05) 6.125,19.75 6.125,19.261 6.625,18.761 6.625,17.539 5.275,16.189 5.275,15.142 4.2,14.067 4.2,8.666 6.666,6.2 11.354,6.2 12.154,7 14.5,7 v1(15.5,8)
  Bottom Layer w0.1: v1(8.15,26.125) 8.625,25.65 10.575,25.65 11.825,26.9 P200.15@11.825,27.55 ; P201.19@14.365,3.55 14.365,4.19 14.975,4.8 14.975,7.475 v1(15.5,8) 15.5,9.25 15.85,9.6 17.1,9.6 17.7,10.2 TPJ3.1@17.7,11.3
  Bottom Layer w0.3: v1(8.15,26.125) P200.9@8.15,27.415
EFR32_PA4: P200.8 P200.16 P201.17 TPJ4.1 U1.37 | length 75.8
  Top Layer w0.1: v1(6.575,19.55) 6.95,19.55 7.1,19.4 U1.37@8.145,19.4
  Signal Layer 3 w0.1: v1@6.625,19.5 v1(6.575,19.55) 6.575,19.933 5.575,20.933 5.575,25.025 6.675,26.125 v1(7.35,26.125) 7.9,25.575 10.375,25.575 10.775,25.975 10.775,26.5 10.6,26.675 10.6,28.985 11.14,29.525 14.958,29.525 15.35,29.133 15.35,28.672 16.195,27.827 17.591,27.827 18.044,27.374 18.044,24.815 18.984,23.875 19.575,23.875 20.297,23.153 20.297,21.006 20.55,20.753 v1(20.55,20.4) ; v1(11.7,9.4) 12.35,10.05 12.35,10.7 13.25,11.6 17.736,11.6 20.264,14.128 20.264,15.463 19.925,15.802 19.925,17.47 20.319,17.864 20.943,17.864 21.265,17.542 21.658,17.542 v1(21.95,17.25)
  Bottom Layer w0.1: v1(7.35,26.125) 7.35,29.2 6.745,29.805 P200.8@6.745,30.45 6.745,31.07 7.325,31.65 11.25,31.65 11.825,31.075 P200.16@11.825,30.45 ; v1(11.7,9.4) 12.475,9.4 12.775,9.1 12.775,8.575 13.675,7.675 13.675,4.75 13.095,4.17 P201.17@13.095,3.55 ; TPJ4.1@19.05,19.55 19.625,20.125 20.275,20.125 v1(20.55,20.4) 21.1,20.4 22.45,19.05 22.45,17.75 v1(21.95,17.25)
EFR32_PA5: P200.10 U1.38 | length 16.1
  Top Layer w0.1: v1(4.875,19.425) 5.908,19.425 6.333,19 U1.38@8.145,19
  Signal Layer 3 w0.1: v1(4.875,19.425) 4.425,19.875 4.425,21.15 4.775,21.5 4.775,25.75 v1(8,28.975)
  Bottom Layer w0.1: v1(8,28.975) 8,30.435 P200.10@8.015,30.45
EFR32_PA6: P200.11 U1.39 | length 16.9
  Top Layer w0.1: v1(5.5,18.925) 6.125,18.925 6.45,18.6 U1.39@8.145,18.6
  Signal Layer 3 w0.1: v1(5.5,18.925) 5.5,19.4 5.075,19.825 4.875,19.825 4.625,20.075 4.625,20.775 4.975,21.125 4.975,25.55 6.55,27.125 8.4,27.125 v1(9.275,26.25) v1@9.275,26.125
  Bottom Layer w0.1: v1@9.275,26.125 v1(9.275,26.25) ; P200.11@9.275,27.54 P200.11@9.285,27.55
  Bottom Layer w0.3: v1(9.275,26.25) P200.11@9.275,27.54
EFR32_PA7: P200.12 U1.40 | length 18.9
  Top Layer w0.1: v1(6.025,18.3) 6.7,18.3 6.8,18.2 U1.40@8.145,18.2
  Signal Layer 3 w0.1: v1(6.025,18.3) 5.5,18.3 4.8,19 4.55,19 4.225,19.325 4.225,21.4 4.575,21.75 4.575,26.227 7.78,29.432 8.368,29.432 v1(8.825,28.975)
  Bottom Layer w0.1: v1(8.825,28.975) 8.825,29.35 9.285,29.81 P200.12@9.285,30.45 P200.12@9.3,30.435
EFR32_PA8: P200.19 P201.31 TPJ5.1 U1.41 | length 82.5
  Top Layer w0.1: v1(4.625,18.575) 5.174,18.575 5.949,17.8 U1.41@8.145,17.8
  Signal Layer 3 w0.1: v1(4.625,18.575) 3.859,18.575 2.6,17.316 2.6,8.003 4.263,6.34 4.263,4.713 4.875,4.1 8.325,4.1 8.95,4.725 8.95,5.15 9.2,5.4 11.685,5.4 12.485,6.2 16.659,6.2 18.989,3.871 21.68,3.871 21.975,3.576 v1(21.975,2.075) ; v1(22.075,5) 23.85,6.775 23.85,8.672 22.697,9.825 21.614,9.825 20.525,10.914 20.525,12.4 21.899,13.774 21.899,14.45 23.042,15.593 23.042,19.547 22.745,19.845 22.745,21.484 v1(22.5,21.729)
  Bottom Layer w0.1: P200.19@14.365,27.55 14.365,26.915 13.575,26.125 13.575,23.525 15.725,21.375 15.841,21.375 16.2,21.016 16.2,20.35 TPJ5.1@15.55,19.7 18.25,19.7 19.125,20.575 19.858,20.575 21.012,21.729 v1(22.5,21.729) ; v1(21.975,2.075) 21.975,3.54 P201.31@21.985,3.55 22.075,3.64 v1(22.075,5)
EFR32_PA9: P200.20 P201.33 TPJ6.1 U1.42 | length 86.3
  Top Layer w0.1: v1(4,18.15) 5.316,18.15 6.066,17.4 U1.42@8.145,17.4
  Signal Layer 3 w0.1: v1(4,18.15) 2.8,16.95 2.8,8.086 4.463,6.423 4.463,4.795 4.958,4.3 8.242,4.3 8.7,4.758 8.7,5.3 9,5.6 11.602,5.6 12.402,6.4 16.742,6.4 19.072,4.071 21.763,4.071 22.175,3.659 22.175,3.175 v1(23.25,2.1) ; v1(16.8,31.975) 19.044,29.731 20.544,29.731 20.9,29.375 20.9,27.542 22.05,26.392 22.05,25.767 21.9,25.617 21.9,24.216 22.5,23.616 v1(22.5,23.575) 22.097,23.172 22.097,22.486 22.395,22.188 22.662,22.188 22.946,21.904 22.946,19.926 23.242,19.63 23.242,15.51 22.099,14.367 22.099,13.691 20.725,12.317 20.725,10.997 21.697,10.025 22.879,10.025 24.05,8.854 24.05,6.615 23.313,5.878 v1(23.312,5.012)
  Bottom Layer w0.1: P200.20@14.365,30.45 14.365,31.065 14.975,31.675 16.5,31.675 v1(16.8,31.975) ; TPJ6.1@19.02,22.07 20.395,22.07 21.9,23.575 v1(22.5,23.575) ; v1(23.25,2.1) 23.25,3.545 P201.33@23.255,3.55 23.312,3.607 v1(23.312,5.012)
EFR32_PA10: P200.21 P201.35 TPJ7.1 U1.43 | length 77.1
  Top Layer w0.1: v1(4.575,17.65) 5.533,17.65 6.008,17.175 7.406,17.175 7.581,17 U1.43@8.145,17
  Signal Layer 3 w0.1: v1(4.575,17.65) 3.867,17.65 3,16.783 3,8.169 4.663,6.506 4.663,4.878 5.041,4.5 8.159,4.5 8.475,4.816 8.475,5.45 8.825,5.8 11.52,5.8 12.32,6.6 16.825,6.6 19.145,4.28 23.78,4.28 v1(24.525,5.025) 24.525,5.7 24.271,5.954 24.271,8.963 23.009,10.225 21.78,10.225 20.925,11.08 20.925,12.234 22.299,13.608 22.299,14.284 23.442,15.428 23.442,19.713 23.146,20.009 23.146,22.054 v1(22.5,22.7)
  Bottom Layer w0.1: P200.21@15.635,27.55 15.925,27.26 15.925,25.287 16.3,24.912 16.3,24 16.025,23.725 16.025,22.495 TPJ7.1@16.49,22.03 17.095,22.03 18.35,20.775 19.648,20.775 21.573,22.7 v1(22.5,22.7) ; P201.35@24.525,3.55 v1(24.525,5.025)
EFR32_PA11: P201.3 U1.44 | length 20.3
  Top Layer w0.1: v1(5.225,17.225) 5.675,17.225 5.925,16.975 7.324,16.975 7.699,16.6 U1.44@8.145,16.6
  Signal Layer 3 w0.1: v1(5.225,17.225) 3.834,17.225 3.2,16.591 3.2,8.251 5.25,6.201 v1(5.25,5)
  Bottom Layer w0.1: P201.3@4.205,3.55 4.205,4.755 4.475,5.025 v1@5.25,5.025
EFR32_PA12: P201.5 U1.45 | length 19.2
  Top Layer w0.1: v1(4.35,16.775) 7.241,16.775 7.7,16.316 7.7,16.3 7.8,16.2 U1.45@8.145,16.2
  Signal Layer 3 w0.1: v1(4.35,16.775) 3.75,16.775 3.4,16.425 3.4,8.334 5.925,5.809 v1(5.925,5)
  Bottom Layer w0.1: P201.5@5.475,3.55 5.475,4.175 5.925,4.625 v1(5.925,5)
EFR32_PA13: P201.7 U1.46 | length 18.6
  Top Layer w0.1: v1(4.5,16.125) 4.825,16.125 5.275,16.575 7.158,16.575 7.5,16.233 7.5,15.925 7.625,15.8 U1.46@8.145,15.8
  Signal Layer 3 w0.1: v1(4.5,16.125) 3.6,15.225 3.6,8.417 6.625,5.392 v1(6.625,5)
  Bottom Layer w0.1: v1(6.625,5) 6.625,3.67 P201.7@6.745,3.55
EFR32_PA14: P201.9 U1.47 | length 19.3
  Top Layer w0.1: v1(4.675,15.45) 5.075,15.45 5.275,15.65 5.275,16.225 5.425,16.375 7.075,16.375 7.3,16.15 7.3,15.725 7.625,15.4 U1.47@8.145,15.4
  Signal Layer 3 w0.1: v1(4.675,15.45) 3.8,14.575 3.8,8.5 6.5,5.8 7.225,5.8 v1@8,5.025
  Bottom Layer w0.1: v1(8,5) 8,3.565 P201.9@8.015,3.55
EFR32_PB0: P200.18 P201.18 U1.31 | length 61.7
  Top Layer w0.1: v1(2.35,21.375) 4.392,21.375 4.947,21.93 9.47,21.93 10.1,21.3 U1.31@10.1,20.955 U1.31@10.1,20.935
  Signal Layer 3 w0.1: v1(9.3,32.2) 8.626,31.526 7.499,31.526 6.623,32.402 5.802,32.402 4.537,31.137 4.537,28.143 2.35,25.956 v1(2.35,21.375) 2.35,20.9 2.15,20.7 2.15,20.697 1.725,20.272 1.725,18.55 1.2,18.025 1.2,7.417 2.863,5.755 2.863,4.112 4.275,2.7 10.725,2.7 v1(13.025,5)
  Bottom Layer w0.1: v1(9.3,32.2) 9.65,31.85 12.35,31.85 13.095,31.105 P200.18@13.095,30.45 ; v1(13.025,5) 13.025,6.38 P201.18@13.095,6.45
EFR32_PB1: P200.25 P201.20 U1.30 | length 68.6
  Top Layer w0.1: v1(2.9,25.2) 2.9,25.143 3.349,24.694 3.349,22.336 3.884,21.8 4.534,21.8 4.864,22.13 9.72,22.13 10.5,21.35 U1.30@10.5,20.955 U1.30@10.5,20.935
  Signal Layer 3 w0.1: v1(14.3,5) 13.9,5.4 12.817,5.4 10.317,2.9 4.358,2.9 3.063,4.195 3.063,5.837 1.4,7.5 1.4,17.933 1.925,18.458 1.925,20.189 2.35,20.614 2.35,20.617 2.8,21.067 2.8,21.7 2.55,21.95 2.55,24.1 2.9,24.45 v1(2.9,25.2) 2.9,26.141 7.42,30.661 16.614,30.661 v1(18.275,29)
  Bottom Layer w0.1: v1(14.3,5) 14.3,6.385 P201.20@14.365,6.45 ; P200.25@18.175,27.55 18.275,27.65 v1(18.275,29)
EFR32_PB2: P200.23 P201.22 U1.29 | length 69
  Top Layer w0.1: v1(3.325,25.825) 3.333,25.817 3.333,25.047 3.549,24.831 3.549,22.418 3.967,22 4.451,22 4.781,22.33 9.87,22.33 10.9,21.3 U1.29@10.9,20.955 U1.29@10.9,20.935
  Signal Layer 3 w0.1: 7.609,30.425 7.474,30.425 3.325,26.275 v1(3.325,25.825) 3.325,24.574 2.75,23.999 2.75,22.033 3,21.783 3,20.984 2.55,20.534 2.55,20.531 2.125,20.106 2.125,18.375 1.6,17.85 1.6,7.583 3.263,5.92 3.263,4.278 4.441,3.1 10.234,3.1 12.734,5.6 15.075,5.6 v1(15.675,5) ; 7.609,30.425 7.734,30.425 ; 7.734,30.425 16.15,30.425 16.95,29.625 16.95,29.025 v1(16.975,29)
  Bottom Layer w0.1: P201.22@15.635,6.45 15.675,6.41 v1(15.675,5) ; P200.23@16.905,27.55 16.975,27.62 v1(16.975,29)
EFR32_PB3: P200.26 P201.24 U1.28 | length 70.5
  Top Layer w0.1: v1(3.75,25.35) 3.75,22.5 4.05,22.2 4.369,22.2 4.699,22.53 9.953,22.53 10.808,21.675 10.925,21.675 11.3,21.3 U1.28@11.3,20.955 U1.28@11.3,20.935
  Signal Layer 3 w0.1: v1(16.925,5) 16.125,5.8 12.651,5.8 10.151,3.3 4.524,3.3 3.463,4.361 3.463,6.009 1.8,7.672 1.8,17.767 2.325,18.292 2.325,20.024 3.2,20.899 3.2,21.866 2.95,22.116 2.95,23.916 3.75,24.716 v1(3.75,25.35) 3.75,26.388 7.566,30.204 15.887,30.204 16.5,29.591 16.5,28.775 16.7,28.575 17.2,28.575 v1(17.625,29)
  Bottom Layer w0.1: P201.24@16.905,6.45 16.925,6.43 v1(16.925,5) ; v1(17.625,29) 17.625,29.3 18.175,29.85 P200.26@18.175,30.45
EFR32_PB4: P201.11 U1.27 | length 35.7
  Top Layer w0.1: v1(4.15,22.73) 10.036,22.73 10.891,21.875 11.15,21.875 11.7,21.325 U1.27@11.7,21.223
  Signal Layer 3 w0.1: v1@4.15,22.715 4.15,21.725 4.025,21.6 4.025,19.05 2.4,17.425 2.4,7.92 4.063,6.258 4.063,4.61 4.772,3.9 8.9,3.9 9.4,4.4 v1(9.4,5)
  Bottom Layer w0.1: P201.11@9.285,3.55 9.4,3.665 v1(9.4,5)
EFR32_PB5: P201.13 U1.26 | length 38.8
  Top Layer w0.1: v1(4.15,23.5) 4.7,22.95 10.099,22.95 10.974,22.075 11.3,22.075 12.1,21.275 U1.26@12.1,21.223
  Signal Layer 3 w0.1: v1(4.15,23.5) 3.75,23.1 3.75,22.25 3.825,22.175 3.825,19.165 2.2,17.54 2.2,7.837 3.863,6.175 3.863,4.527 4.689,3.7 9.486,3.7 v1@10.782,4.996
  Bottom Layer w0.1: P201.13@10.555,3.55 10.782,3.777 v1@10.782,4.996
  other v1: 10.782,5
EFR32_PC0: P201.38 SW1.6 U1.3 | length 44
  Top Layer w0.1: U1.3@16.055,14.6 18.134,14.6 19.009,13.725 v1(21.275,13.725)
  Top Layer w0.2: SW1.6@12.75,33.6 12.9,33.6 v1(13.176,33.324)
  Signal Layer 3 w0.1: v1(13.176,33.324) 13.176,32.497 14.223,31.45 17.033,31.45 17.042,31.441 17.049,31.441 17.051,31.44 17.052,31.44 18.962,29.531 20.462,29.531 20.7,29.292 20.7,27.459 21.85,26.309 21.85,25.85 21.675,25.675 21.675,24.158 21.897,23.936 21.897,21.699 22.542,21.054 22.542,19.765 22.842,19.464 22.842,15.676 21.275,14.109 v1(21.275,13.725) 20.325,12.775 20.325,10.831 21.531,9.625 22.275,9.625 v1(23.375,8.525)
  Bottom Layer w0.1: v1(23.375,8.525) 23.875,8.025 24.825,8.025 25.795,7.055 P201.38@25.795,6.45
EFR32_PC1: P200.29 U1.4 U203.D2 | length 23.1
  Top Layer w0.1: U1.4@16.055,15 16.55,15 16.75,14.8 18.217,14.8 18.892,14.125 v1(19.625,14.125) ; v1(18.85,15.6) 19.426,15.6 19.601,15.425 U203.D2@19.975,15.425
  Signal Layer 3 w0.1: v1(18.85,15.6) 19.725,15.6 ; v1(19.625,14.125) 20.064,14.564 20.064,15.261 19.725,15.6 ; v1(20.7,26.15) 20.7,25.508 20.9,25.308 20.9,24.342 21.497,23.745 21.497,21.503 22.142,20.858 22.142,19.599 22.428,19.313 22.428,18.078 22.125,17.775 21.478,17.775 21.187,18.066 20.168,18.066 19.725,17.623 19.725,15.6
  Bottom Layer w0.3: v1(20.7,26.15) P200.29@20.7,27.535
EFR32_PC2: U1.5 U203.C3 | length 4.6
  Top Layer w0.1: U1.5@16.055,15.4 16.433,15.4 16.833,15 18.3,15 18.7,14.6 19.7,14.6 U203.C3@20.175,15.075
EFR32_PC3: P200.28 U1.7 U203.E1 | length 21.1
  Top Layer w0.1: U1.7@16.055,16.2 18.7,16.2 18.8,16.1 v1(19.3,16.1) 19.45,16.1 U203.E1@19.775,15.775
  Signal Layer 3 w0.1: v1@19.35,16.1 19.35,17.562 20.054,18.266 21.341,18.266 21.975,18.9 21.975,19.2 21.742,19.433 21.742,20.692 21.097,21.338 21.097,23.545 20.5,24.142 20.5,25.142 20.075,25.567 20.075,26.75 19.45,27.375 v1(19.45,29.025)
  Bottom Layer w0.1: P200.28@19.445,30.45 P200.28@19.45,30.445
  Bottom Layer w0.3: v1(19.45,29.025) P200.28@19.45,30.445
EFR32_PC4: R218.1 U1.8 U203.A3 | length 10.7
  Top Layer w0.1: U1.8@16.055,16.6 16.75,16.6 16.825,16.525 19.8,16.525 20.125,16.2 20.8,16.2 21,16.4 22.55,16.4 22.725,16.225 22.725,15.668 22.482,15.425 R218.1@21.975,15.425 21.975,14.813 21.739,14.577 21.073,14.577 U203.A3@20.575,15.075
EFR32_PC5: P201.15 U1.9 | length 24.1
  Top Layer w0.1: U1.9@16.055,17 16.667,17 16.942,16.725 19.975,16.725 20.1,16.6 v1(20.525,16.6)
  Signal Layer 3 w0.1: v1(12.35,8.75) 12.75,9.15 12.75,10.534 13.416,11.2 17.901,11.2 20.664,13.963 20.664,15.986 20.525,16.125 v1(20.525,16.6)
  Bottom Layer w0.1: P201.15@11.825,3.55 11.825,4.175 12.45,4.8 12.45,7.55 12.35,7.65 v1(12.35,8.75)
EFR32_PC6: P200.31 P201.36 U1.10 | length 31.5
  Top Layer w0.1: U1.10@16.055,17.4 16.55,17.4 17.025,16.925 20.089,16.925 20.164,17 v1(21.225,17)
  Signal Layer 3 w0.1: v1(21.225,17) 21.225,16.466 ; v1(21.325,26.15) 21.325,24.225 21.697,23.853 21.697,21.616 22.342,20.971 22.342,19.682 22.628,19.396 22.628,17.185 22.185,16.742 21.838,16.742 21.562,16.466 21.225,16.466 ; v1(22.65,8.525) 21.75,9.425 21.449,9.425 20.125,10.749 20.125,13.141 20.864,13.88 20.864,16.106 21.225,16.466
  Bottom Layer w0.1: v1(22.65,8.525) 23.425,7.75 23.875,7.75 24.525,7.1 P201.36@24.525,6.45
  Bottom Layer w0.2: v1(21.325,26.15) 21.985,26.81 P200.31@21.985,27.55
